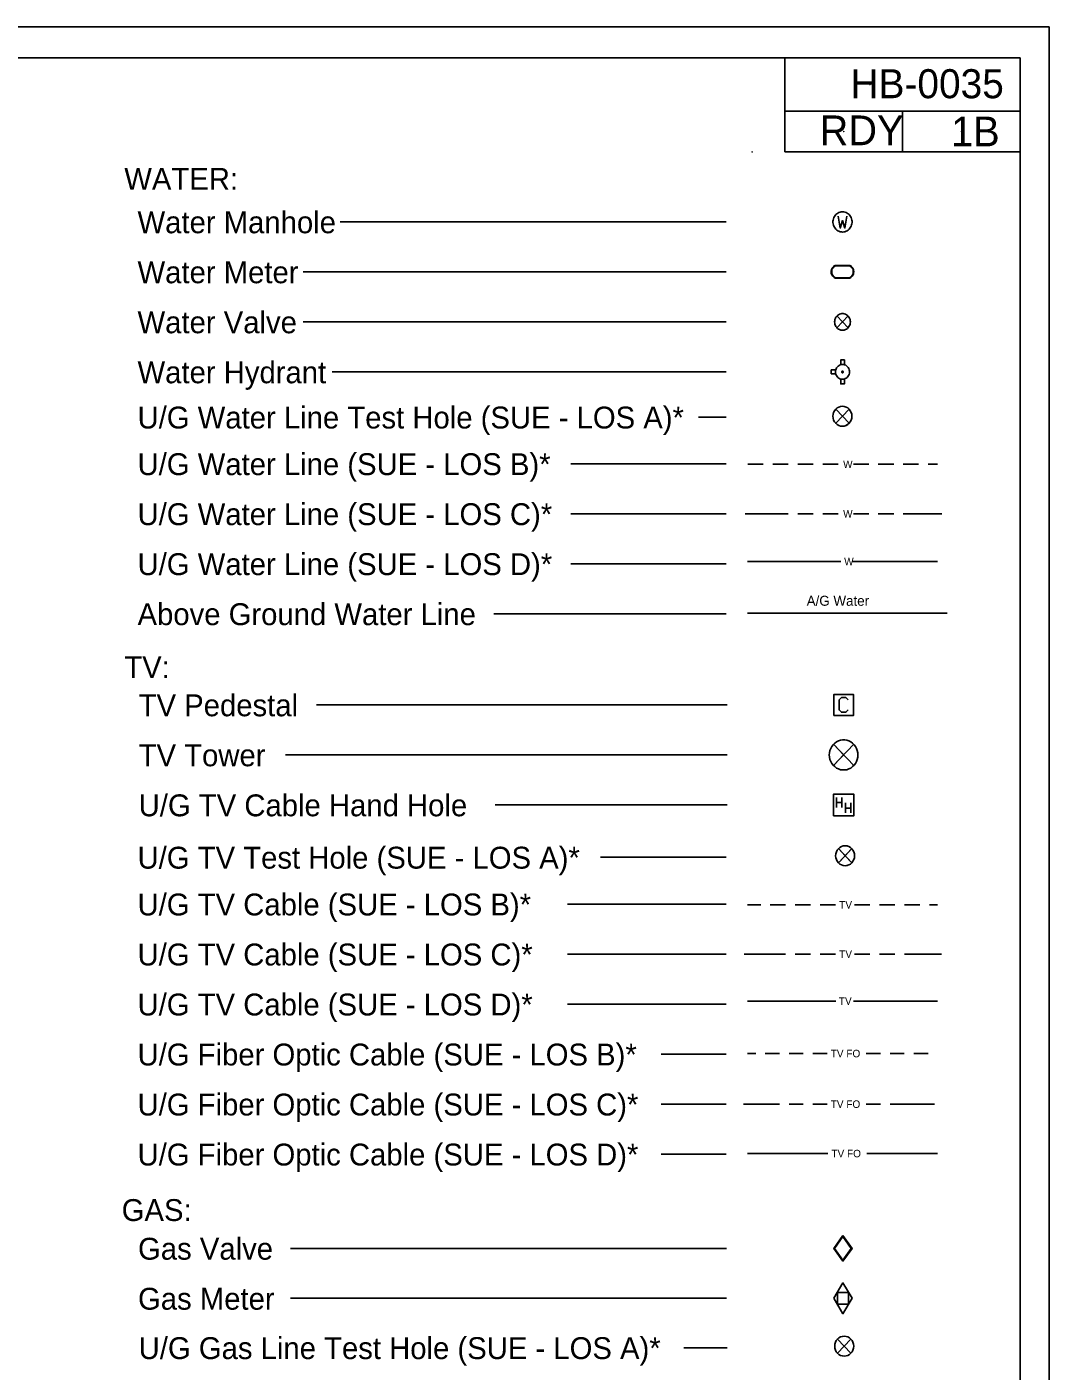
# Model space of a CAD drawing. Extents: x 2025847 to 2026166, y 840763 to 840870.
# Drawn here: x 2026130.13 to 2026165.55, y 840823.5 to 840870.09 of the extents above; entities that cross this region are included whole.
import ezdxf

# ---------------------------------------------------------------- set-up
doc = ezdxf.new("R2010")
doc.units = 0
for name, color, linetype in [('Exist Utilities Gas Test Hole SUE LOS A CELL', 7, 'Continuous'), ('Exist Utilities TV Test Hole SUE LOS A CELL', 7, 'Continuous'), ('Exist Utilities Water Test Hole SUE LOS A CELL', 7, 'Continuous'), ('Sheet_Plan', 7, 'Continuous'), ('Sheet_Plot_Border_Outside_CELL', 7, 'Continuous'), ('Sheet_Symbology', 7, 'Continuous'), ('Sheet_Title_Block_Text', 7, 'Continuous'), ('z - Construction', 7, 'Continuous')]:
    doc.layers.add(name, color=color, linetype=linetype)

msp = doc.modelspace()

# ---------------------------------------------------------------- linework, layer by layer
at = {"layer": 'Exist Utilities Gas Test Hole SUE LOS A CELL'}
for points in [[(2026158.679, 840824.614), (2026158.213, 840824.124), (2026158.446, 840824.369), (2026158.213, 840824.614), (2026158.679, 840824.124)], [(2026158.213, 840824.614), (2026158.446, 840824.369), (2026158.679, 840824.614)], [(2026158.679, 840824.124), (2026158.446, 840824.369), (2026158.213, 840824.124)]]:
    msp.add_lwpolyline(points, dxfattribs=at)
msp.add_ellipse((2026158.446, 840824.369), major_axis=(0, -0.346), ratio=0.95, dxfattribs=at)
for start_param, end_param in [(2.356194, 3.926991), (5.497787, 7.068583)]:
    msp.add_ellipse((2026158.446, 840824.369), major_axis=(0, -0.346), ratio=0.95, start_param=start_param, end_param=end_param, dxfattribs=at)
at = {"layer": 'Exist Utilities TV Test Hole SUE LOS A CELL'}
for points in [[(2026158.711, 840841.609), (2026158.246, 840841.12), (2026158.478, 840841.364), (2026158.246, 840841.609), (2026158.711, 840841.12)], [(2026158.246, 840841.609), (2026158.478, 840841.364), (2026158.711, 840841.609)], [(2026158.711, 840841.12), (2026158.478, 840841.364), (2026158.246, 840841.12)]]:
    msp.add_lwpolyline(points, dxfattribs=at)
msp.add_ellipse((2026158.478, 840841.364), major_axis=(0, -0.346), ratio=0.95, dxfattribs=at)
for start_param, end_param in [(2.356194, 3.926991), (5.497787, 7.068583)]:
    msp.add_ellipse((2026158.478, 840841.364), major_axis=(0, -0.346), ratio=0.95, start_param=start_param, end_param=end_param, dxfattribs=at)
at = {"layer": 'Exist Utilities Water Test Hole SUE LOS A CELL'}
for points in [[(2026158.617, 840856.838), (2026158.152, 840856.348), (2026158.384, 840856.593), (2026158.152, 840856.838), (2026158.617, 840856.348)], [(2026158.152, 840856.838), (2026158.384, 840856.593), (2026158.617, 840856.838)], [(2026158.617, 840856.348), (2026158.384, 840856.593), (2026158.152, 840856.348)]]:
    msp.add_lwpolyline(points, dxfattribs=at)
msp.add_ellipse((2026158.384, 840856.593), major_axis=(0, -0.346), ratio=0.95, dxfattribs=at)
for start_param, end_param in [(2.356194, 3.926991), (5.497787, 7.068583)]:
    msp.add_ellipse((2026158.384, 840856.593), major_axis=(0, -0.346), ratio=0.95, start_param=start_param, end_param=end_param, dxfattribs=at)
at = {"layer": 'Sheet_Plan'}
for p, q in [((2026164.548, 840869.009), (2026024.668, 840869.009)), ((2026156.389, 840865.752), (2026156.389, 840869.009)), ((2026164.546, 840780.981), (2026164.548, 840869.009)), ((2026164.548, 840867.169), (2026156.389, 840867.169)), ((2026160.468, 840865.752), (2026160.468, 840867.169)), ((2026164.548, 840865.752), (2026156.389, 840865.752))]:
    msp.add_line(p, q, dxfattribs=at)
msp.add_ellipse((2026155.256, 840865.752), major_axis=(0, 0.00515), ratio=0.95, dxfattribs=at)
at = {"layer": 'Sheet_Plot_Border_Outside_CELL'}
msp.add_lwpolyline([(2026023.879, 840870.085), (2026165.546, 840870.085), (2026165.546, 840778.419), (2026023.879, 840778.419)], close=True, dxfattribs=at)
at = {"layer": 'Sheet_Symbology'}
for p, q in [((2026154.353, 840863.328), (2026140.985, 840863.328)), ((2026154.353, 840861.595), (2026139.697, 840861.595)), ((2026158.136, 840861.818), (2026158.642, 840861.818)), ((2026158.136, 840861.801), (2026158.642, 840861.801)), ((2026158.638, 840861.394), (2026158.136, 840861.394)), ((2026158.638, 840861.376), (2026158.136, 840861.376)), ((2026154.353, 840859.862), (2026139.697, 840859.862)), ((2026154.353, 840858.129), (2026140.706, 840858.129)), ((2026154.353, 840856.562), (2026153.402, 840856.562)), ((2026154.353, 840854.947), (2026148.971, 840854.947)), ((2026155.108, 840854.928), (2026155.643, 840854.928)), ((2026155.972, 840854.928), (2026156.507, 840854.928)), ((2026156.837, 840854.928), (2026157.372, 840854.928)), ((2026157.701, 840854.928), (2026158.236, 840854.928)), ((2026158.763, 840854.928), (2026159.298, 840854.928)), ((2026159.627, 840854.928), (2026160.162, 840854.928)), ((2026160.491, 840854.928), (2026161.026, 840854.928)), ((2026161.356, 840854.928), (2026161.68, 840854.928)), ((2026154.353, 840853.214), (2026148.971, 840853.214)), ((2026155.015, 840853.214), (2026156.507, 840853.214)), ((2026156.837, 840853.214), (2026157.372, 840853.214)), ((2026157.701, 840853.214), (2026158.236, 840853.214)), ((2026158.763, 840853.214), (2026159.298, 840853.214)), ((2026159.627, 840853.214), (2026160.162, 840853.214)), ((2026160.491, 840853.214), (2026161.834, 840853.214)), ((2026154.353, 840851.481), (2026148.971, 840851.481)), ((2026155.095, 840851.557), (2026158.33, 840851.557)), ((2026158.741, 840851.557), (2026161.68, 840851.557)), ((2026154.353, 840849.748), (2026146.309, 840849.748)), ((2026155.095, 840849.766), (2026162.01, 840849.766)), ((2026154.392, 840846.59), (2026140.158, 840846.59)), ((2026158.375, 840846.335), (2026158.481, 840846.335)), ((2026154.392, 840844.857), (2026139.094, 840844.857)), ((2026158.174, 840843.386), (2026158.174, 840843.037)), ((2026158.364, 840843.386), (2026158.364, 840843.037)), ((2026154.392, 840843.124), (2026146.349, 840843.124)), ((2026158.174, 840843.208), (2026158.364, 840843.208)), ((2026158.491, 840843.196), (2026158.491, 840842.847)), ((2026158.491, 840843.018), (2026158.68, 840843.018)), ((2026158.68, 840843.196), (2026158.68, 840842.847)), ((2026154.353, 840841.31), (2026150.001, 840841.31)), ((2026154.353, 840839.688), (2026148.863, 840839.688)), ((2026155.095, 840839.66), (2026155.553, 840839.66)), ((2026155.883, 840839.66), (2026156.418, 840839.66)), ((2026156.747, 840839.66), (2026157.282, 840839.66)), ((2026157.611, 840839.66), (2026158.146, 840839.66)), ((2026158.805, 840839.66), (2026159.34, 840839.66)), ((2026159.669, 840839.66), (2026160.204, 840839.66)), ((2026160.534, 840839.66), (2026161.069, 840839.66)), ((2026161.398, 840839.66), (2026161.68, 840839.66)), ((2026154.353, 840837.955), (2026148.863, 840837.955)), ((2026154.981, 840837.955), (2026156.418, 840837.955)), ((2026156.747, 840837.955), (2026157.282, 840837.955)), ((2026157.611, 840837.955), (2026158.146, 840837.955)), ((2026158.805, 840837.955), (2026159.34, 840837.955)), ((2026159.669, 840837.955), (2026160.204, 840837.955)), ((2026160.534, 840837.955), (2026161.818, 840837.955)), ((2026154.353, 840836.222), (2026148.863, 840836.222)), ((2026155.095, 840836.327), (2026158.155, 840836.327)), ((2026158.772, 840836.327), (2026161.68, 840836.327)), ((2026155.095, 840834.51), (2026155.383, 840834.51)), ((2026155.712, 840834.51), (2026156.206, 840834.51)), ((2026156.535, 840834.51), (2026157.029, 840834.51)), ((2026157.358, 840834.51), (2026157.852, 840834.51)), ((2026159.21, 840834.51), (2026159.704, 840834.51)), ((2026160.034, 840834.51), (2026160.527, 840834.51)), ((2026160.857, 840834.51), (2026161.351, 840834.51)), ((2026154.353, 840834.489), (2026152.11, 840834.489)), ((2026154.353, 840832.756), (2026152.11, 840832.756)), ((2026154.959, 840832.756), (2026156.206, 840832.756)), ((2026156.535, 840832.756), (2026157.029, 840832.756)), ((2026157.358, 840832.756), (2026157.852, 840832.756)), ((2026159.21, 840832.756), (2026159.704, 840832.756)), ((2026160.034, 840832.756), (2026161.575, 840832.756)), ((2026154.353, 840831.023), (2026152.11, 840831.023)), ((2026155.095, 840831.044), (2026157.876, 840831.044)), ((2026159.234, 840831.044), (2026161.68, 840831.044)), ((2026158.404, 840828.168), (2026158.115, 840827.759)), ((2026158.693, 840827.759), (2026158.404, 840828.168)), ((2026154.37, 840827.759), (2026139.265, 840827.759)), ((2026158.115, 840827.759), (2026158.404, 840827.351)), ((2026158.404, 840827.351), (2026158.693, 840827.759)), ((2026154.37, 840826.027), (2026139.265, 840826.027)), ((2026154.392, 840824.316), (2026152.889, 840824.316))]:
    msp.add_line(p, q, dxfattribs=at)
for points in [[(2026158.387, 840863.68), (2026158.344, 840863.677), (2026158.304, 840863.669), (2026158.264, 840863.655), (2026158.227, 840863.635), (2026158.192, 840863.613), (2026158.16, 840863.585), (2026158.13, 840863.551), (2026158.106, 840863.517), (2026158.085, 840863.478), (2026158.072, 840863.435), (2026158.061, 840863.393), (2026158.056, 840863.351), (2026158.056, 840863.306), (2026158.061, 840863.264), (2026158.072, 840863.219), (2026158.085, 840863.179), (2026158.106, 840863.14), (2026158.13, 840863.106), (2026158.16, 840863.072), (2026158.192, 840863.044), (2026158.227, 840863.022), (2026158.264, 840863.002), (2026158.304, 840862.988), (2026158.347, 840862.979), (2026158.387, 840862.977), (2026158.43, 840862.979), (2026158.47, 840862.988), (2026158.51, 840863.002), (2026158.548, 840863.022), (2026158.582, 840863.044), (2026158.614, 840863.072), (2026158.644, 840863.106), (2026158.668, 840863.14), (2026158.689, 840863.179), (2026158.703, 840863.221), (2026158.713, 840863.264), (2026158.719, 840863.306), (2026158.719, 840863.351), (2026158.713, 840863.393), (2026158.703, 840863.438), (2026158.689, 840863.478), (2026158.668, 840863.517), (2026158.644, 840863.551), (2026158.614, 840863.585), (2026158.582, 840863.613), (2026158.548, 840863.635), (2026158.51, 840863.655), (2026158.47, 840863.669), (2026158.427, 840863.677), (2026158.387, 840863.68)], [(2026158.237, 840863.523), (2026158.307, 840863.112), (2026158.387, 840863.371), (2026158.47, 840863.112), (2026158.54, 840863.523)], [(2026158.136, 840861.818), (2026158.103, 840861.801), (2026158.073, 840861.776), (2026158.047, 840861.745), (2026158.027, 840861.714), (2026158.01, 840861.675), (2026158, 840861.637), (2026157.997, 840861.599), (2026158, 840861.557), (2026158.01, 840861.519), (2026158.027, 840861.484), (2026158.047, 840861.449), (2026158.073, 840861.421), (2026158.103, 840861.397), (2026158.136, 840861.376)], [(2026158.143, 840861.804), (2026158.11, 840861.783), (2026158.08, 840861.759), (2026158.053, 840861.728), (2026158.033, 840861.696), (2026158.02, 840861.658), (2026158.014, 840861.616), (2026158.014, 840861.578), (2026158.02, 840861.54), (2026158.033, 840861.501), (2026158.053, 840861.467), (2026158.08, 840861.435), (2026158.11, 840861.411), (2026158.143, 840861.394)], [(2026158.632, 840861.804), (2026158.668, 840861.787), (2026158.698, 840861.759), (2026158.721, 840861.731), (2026158.741, 840861.696), (2026158.754, 840861.658), (2026158.761, 840861.616), (2026158.761, 840861.578), (2026158.754, 840861.536), (2026158.741, 840861.501), (2026158.721, 840861.467), (2026158.695, 840861.435), (2026158.665, 840861.411), (2026158.632, 840861.39)], [(2026158.638, 840861.818), (2026158.672, 840861.801), (2026158.701, 840861.776), (2026158.728, 840861.745), (2026158.747, 840861.714), (2026158.764, 840861.675), (2026158.774, 840861.637), (2026158.777, 840861.599), (2026158.774, 840861.557), (2026158.764, 840861.519), (2026158.747, 840861.484), (2026158.728, 840861.449), (2026158.701, 840861.421), (2026158.672, 840861.397), (2026158.638, 840861.376)], [(2026158.661, 840859.862), (2026158.658, 840859.904), (2026158.649, 840859.949), (2026158.633, 840859.987), (2026158.612, 840860.026), (2026158.588, 840860.058), (2026158.557, 840860.086), (2026158.524, 840860.112), (2026158.487, 840860.131), (2026158.448, 840860.144), (2026158.408, 840860.15), (2026158.366, 840860.15), (2026158.326, 840860.144), (2026158.287, 840860.131), (2026158.25, 840860.112), (2026158.217, 840860.086), (2026158.187, 840860.058), (2026158.162, 840860.026), (2026158.141, 840859.987), (2026158.126, 840859.949), (2026158.117, 840859.904), (2026158.114, 840859.862), (2026158.117, 840859.821), (2026158.126, 840859.776), (2026158.141, 840859.738), (2026158.162, 840859.699), (2026158.187, 840859.667), (2026158.217, 840859.639), (2026158.25, 840859.613), (2026158.287, 840859.594), (2026158.326, 840859.581), (2026158.366, 840859.575), (2026158.408, 840859.575), (2026158.448, 840859.581), (2026158.487, 840859.594), (2026158.524, 840859.613), (2026158.557, 840859.639), (2026158.588, 840859.667), (2026158.612, 840859.699), (2026158.633, 840859.738), (2026158.649, 840859.776), (2026158.658, 840859.821), (2026158.661, 840859.862)], [(2026158.582, 840859.658), (2026158.193, 840860.067), (2026158.387, 840859.862), (2026158.193, 840859.658), (2026158.582, 840860.067)], [(2026158.384, 840858.386), (2026158.346, 840858.382), (2026158.308, 840858.372), (2026158.27, 840858.356), (2026158.239, 840858.332), (2026158.21, 840858.306), (2026158.185, 840858.273), (2026158.166, 840858.236), (2026158.153, 840858.196), (2026158.144, 840858.156), (2026158.144, 840858.116), (2026158.15, 840858.076), (2026158.16, 840858.036), (2026158.179, 840858), (2026158.201, 840857.967), (2026158.229, 840857.937), (2026158.261, 840857.91), (2026158.295, 840857.893), (2026158.334, 840857.88), (2026158.371, 840857.873), (2026158.409, 840857.873), (2026158.447, 840857.88), (2026158.485, 840857.897), (2026158.52, 840857.913), (2026158.551, 840857.94), (2026158.577, 840857.97), (2026158.599, 840858.003), (2026158.615, 840858.043), (2026158.627, 840858.083), (2026158.63, 840858.123), (2026158.627, 840858.163), (2026158.621, 840858.203), (2026158.605, 840858.243), (2026158.586, 840858.279), (2026158.561, 840858.309), (2026158.529, 840858.336), (2026158.498, 840858.359), (2026158.46, 840858.372), (2026158.422, 840858.382), (2026158.384, 840858.386)], [(2026158.327, 840858.379), (2026158.327, 840858.545), (2026158.454, 840858.545), (2026158.454, 840858.376)], [(2026158.153, 840858.196), (2026157.995, 840858.196), (2026157.995, 840858.063), (2026158.153, 840858.063)], [(2026158.327, 840857.88), (2026158.327, 840857.714), (2026158.454, 840857.714), (2026158.454, 840857.883)], [(2026158.387, 840858.159), (2026158.375, 840858.156), (2026158.365, 840858.146), (2026158.359, 840858.133), (2026158.362, 840858.119), (2026158.368, 840858.106), (2026158.381, 840858.1), (2026158.394, 840858.1), (2026158.406, 840858.106), (2026158.412, 840858.119), (2026158.416, 840858.133), (2026158.409, 840858.146), (2026158.4, 840858.156), (2026158.387, 840858.159)], [(2026158.084, 840846.229), (2026158.77, 840846.229), (2026158.77, 840846.951), (2026158.084, 840846.951), (2026158.084, 840846.229)], [(2026158.587, 840846.415), (2026158.506, 840846.335), (2026158.348, 840846.335), (2026158.271, 840846.415), (2026158.271, 840846.765), (2026158.348, 840846.845), (2026158.506, 840846.845), (2026158.587, 840846.765)], [(2026158.922, 840844.857), (2026158.917, 840844.932), (2026158.9, 840845.013), (2026158.873, 840845.083), (2026158.834, 840845.153), (2026158.79, 840845.211), (2026158.735, 840845.263), (2026158.675, 840845.309), (2026158.608, 840845.344), (2026158.537, 840845.367), (2026158.465, 840845.379), (2026158.388, 840845.379), (2026158.316, 840845.367), (2026158.245, 840845.344), (2026158.178, 840845.309), (2026158.118, 840845.263), (2026158.063, 840845.211), (2026158.019, 840845.153), (2026157.98, 840845.083), (2026157.953, 840845.013), (2026157.936, 840844.932), (2026157.931, 840844.857), (2026157.936, 840844.782), (2026157.953, 840844.7), (2026157.98, 840844.631), (2026158.019, 840844.561), (2026158.063, 840844.503), (2026158.118, 840844.451), (2026158.178, 840844.404), (2026158.245, 840844.37), (2026158.316, 840844.346), (2026158.388, 840844.335), (2026158.465, 840844.335), (2026158.537, 840844.346), (2026158.608, 840844.37), (2026158.675, 840844.404), (2026158.735, 840844.451), (2026158.79, 840844.503), (2026158.834, 840844.561), (2026158.873, 840844.631), (2026158.9, 840844.7), (2026158.917, 840844.782), (2026158.922, 840844.857)], [(2026158.779, 840844.486), (2026158.074, 840845.228), (2026158.427, 840844.857), (2026158.074, 840844.486), (2026158.779, 840845.228)], [(2026158.072, 840842.751), (2026158.781, 840842.751), (2026158.781, 840843.497), (2026158.072, 840843.497), (2026158.072, 840842.751)], [(2026158.404, 840828.203), (2026158.09, 840827.759), (2026158.404, 840827.316), (2026158.718, 840827.759), (2026158.404, 840828.203)], [(2026158.09, 840826.027), (2026158.404, 840826.562), (2026158.718, 840826.027), (2026158.404, 840825.492), (2026158.09, 840826.027)], [(2026158.21, 840826.227), (2026158.598, 840826.227), (2026158.598, 840825.822), (2026158.21, 840825.822), (2026158.21, 840826.227)]]:
    msp.add_lwpolyline(points, dxfattribs=at)
at = {"layer": 'z - Construction'}
for p, q in [((2026165.546, 840870.085), (2026023.879, 840870.085)), ((2026165.546, 840778.419), (2026165.546, 840870.085))]:
    msp.add_line(p, q, dxfattribs=at)
for centre in [(2026159.335, 840868.089), (2026158.429, 840866.461), (2026162.508, 840866.461)]:
    msp.add_ellipse(centre, major_axis=(0, 0.00515), ratio=0.95, dxfattribs=at)

# ---------------------------------------------------------------- texts
at = {"layer": 'Sheet_Symbology'}
for s, height, p in [('WATER:', 0.7582, (2026133.504, 840864.441)), ('Water Manhole', 0.75818, (2026133.963, 840862.935)), ('Water Meter', 0.75818, (2026133.963, 840861.202)), ('Water Valve', 0.75818, (2026133.963, 840859.469)), ('Water Hydrant', 0.75818, (2026133.963, 840857.736)), ('U/G Water Line Test Hole (SUE - LOS A)*', 0.75818, (2026133.963, 840856.169)), ('U/G Water Line (SUE - LOS B)*', 0.75818, (2026133.963, 840854.553)), ('W', 0.26, (2026158.409, 840854.798)), ('U/G Water Line (SUE - LOS C)*', 0.75818, (2026133.963, 840852.82)), ('W', 0.26, (2026158.409, 840853.084)), ('U/G Water Line (SUE - LOS D)*', 0.75818, (2026133.963, 840851.088)), ('W', 0.26, (2026158.445, 840851.427)), ('A/G Water', 0.3466, (2026157.146, 840850.026)), ('Above Ground Water Line', 0.75818, (2026133.963, 840849.355)), ('TV:', 0.7582, (2026133.504, 840847.521)), ('TV Pedestal', 0.75818, (2026134.002, 840846.197)), ('TV Tower', 0.7582, (2026134.002, 840844.464)), ('U/G TV Cable Hand Hole', 0.75818, (2026134.002, 840842.731)), ('U/G TV Test Hole (SUE - LOS A)*', 0.75818, (2026133.963, 840840.917)), ('U/G TV Cable (SUE - LOS B)*', 0.75818, (2026133.963, 840839.295)), ('TV', 0.2599, (2026158.274, 840839.53)), ('U/G TV Cable (SUE - LOS C)*', 0.75818, (2026133.963, 840837.562)), ('TV', 0.2599, (2026158.274, 840837.825)), ('U/G TV Cable (SUE - LOS D)*', 0.75818, (2026133.963, 840835.829)), ('TV', 0.2599, (2026158.262, 840836.197)), ('U/G Fiber Optic Cable (SUE - LOS B)*', 0.75818, (2026133.963, 840834.096)), ('TV FO', 0.2599, (2026157.98, 840834.38)), ('U/G Fiber Optic Cable (SUE - LOS C)*', 0.75818, (2026133.963, 840832.363)), ('TV FO', 0.2599, (2026157.98, 840832.626)), ('U/G Fiber Optic Cable (SUE - LOS D)*', 0.75818, (2026133.963, 840830.63)), ('TV FO', 0.2599, (2026158.003, 840830.914)), ('GAS:', 0.7582, (2026133.414, 840828.706)), ('Gas Valve', 0.7582, (2026133.98, 840827.366)), ('Gas Meter', 0.7582, (2026133.98, 840825.633)), ('U/G Gas Line Test Hole (SUE - LOS A)*', 0.75818, (2026134.002, 840823.922))]:
    msp.add_text(s, height=height, dxfattribs=at).set_placement(p)
at = {"layer": 'Sheet_Title_Block_Text'}
for s, height, p in [('HB-0035', 1.0066, (2026158.664, 840867.613)), ('RDY', 1.0306, (2026157.593, 840865.985)), ('1B', 1.0306, (2026162.148, 840865.946))]:
    msp.add_text(s, height=height, dxfattribs=at).set_placement(p)

doc.saveas('drawing.dxf')
